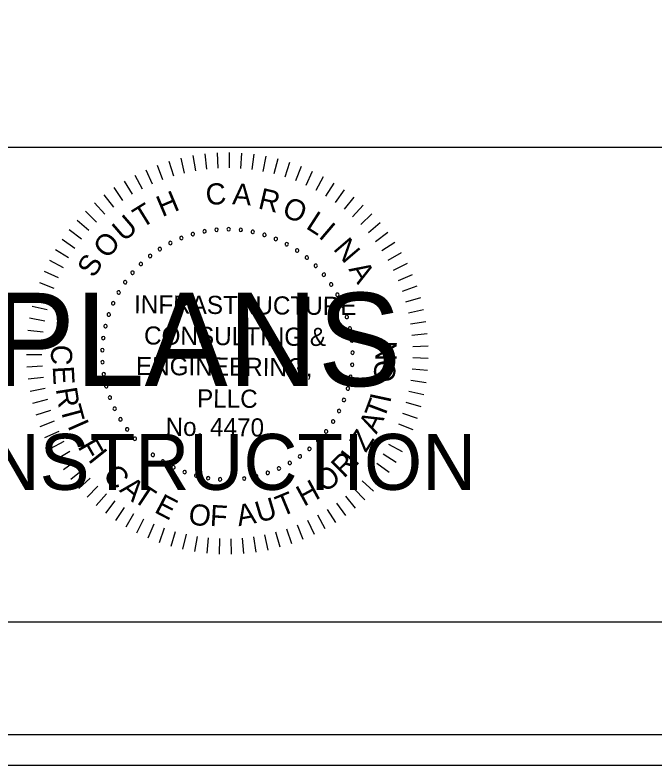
# Model space of a CAD drawing. Extents: x 967 to 1326, y 964 to 3704.
# Drawn here: x 1189.3 to 1212.88, y 963.72 to 991.36 of the extents above; entities that cross this region are included whole.
import ezdxf

# ---------------------------------------------------------------- set-up
doc = ezdxf.new("R2010")
doc.units = 0
for name, color, linetype in [('RD_SHT_Bndy', 7, 'Continuous'), ('RD_SHT_IplotShp', 7, 'Continuous'), ('RD_SHT_Misc1', 7, 'Continuous'), ('RD_SHT_Misc2', 7, 'Continuous'), ('RD_XS_TX_Station', 7, 'Continuous')]:
    doc.layers.add(name, color=color, linetype=linetype)

msp = doc.modelspace()

# ---------------------------------------------------------------- linework, layer by layer
at = {"layer": 'RD_SHT_Bndy'}
for p, q in [((996.114, 986.486), (1323.886, 986.486)), ((1323.886, 968.983), (996.114, 968.983))]:
    msp.add_line(p, q, dxfattribs=at)
at = {"layer": 'RD_SHT_IplotShp'}
for points in [[(967.409, 963.72), (1326.285, 963.72), (1326.285, 1183.72), (967.409, 1183.72)], [(988.525, 964.84), (1326.285, 964.84), (1326.285, 1182.6), (988.525, 1182.6)]]:
    msp.add_lwpolyline(points, close=True, dxfattribs=at)
at = {"layer": 'RD_SHT_Misc1'}
for p, q in [((1196.292, 986.245), (1196.357, 985.68)), ((1196.742, 986.282), (1196.772, 985.714)), ((1197.194, 986.292), (1197.189, 985.723)), ((1197.645, 986.274), (1197.606, 985.706)), ((1198.094, 986.228), (1198.02, 985.664)), ((1194.968, 985.971), (1195.134, 985.427)), ((1195.403, 986.09), (1195.536, 985.536)), ((1195.846, 986.181), (1195.945, 985.62)), ((1198.54, 986.156), (1198.432, 985.596)), ((1198.98, 986.056), (1198.838, 985.504)), ((1199.414, 985.929), (1199.238, 985.387)), ((1194.122, 985.656), (1194.353, 985.136)), ((1194.54, 985.827), (1194.739, 985.293)), ((1199.839, 985.777), (1199.63, 985.246)), ((1193.715, 985.461), (1193.978, 984.956)), ((1200.253, 985.598), (1200.013, 985.082)), ((1200.656, 985.395), (1200.385, 984.894)), ((1193.321, 985.241), (1193.614, 984.752)), ((1201.047, 985.167), (1200.745, 984.684)), ((1192.94, 984.997), (1193.263, 984.528)), ((1201.422, 984.917), (1201.092, 984.453)), ((1192.576, 984.731), (1192.926, 984.282)), ((1201.781, 984.643), (1201.424, 984.2)), ((1192.228, 984.443), (1192.605, 984.016)), ((1202.124, 984.349), (1201.739, 983.928)), ((1191.899, 984.134), (1192.301, 983.731)), ((1202.447, 984.034), (1202.038, 983.638)), ((1191.589, 983.805), (1192.015, 983.428)), ((1202.751, 983.7), (1202.318, 983.329)), ((1191.299, 983.459), (1191.748, 983.108)), ((1203.034, 983.348), (1202.579, 983.004)), ((1191.032, 983.095), (1191.501, 982.772)), ((1203.294, 982.979), (1202.82, 982.664)), ((1190.787, 982.716), (1191.274, 982.422)), ((1203.532, 982.595), (1203.04, 982.31)), ((1190.565, 982.323), (1191.07, 982.059)), ((1203.746, 982.198), (1203.237, 981.943)), ((1190.368, 981.916), (1190.888, 981.684)), ((1203.936, 981.788), (1203.412, 981.564)), ((1190.196, 981.499), (1190.729, 981.299)), ((1204.1, 981.367), (1203.563, 981.176)), ((1190.05, 981.072), (1190.594, 980.905)), ((1204.238, 980.937), (1203.691, 980.779)), ((1189.93, 980.636), (1190.484, 980.503)), ((1204.349, 980.5), (1203.794, 980.375)), ((1189.837, 980.195), (1190.398, 980.095)), ((1204.434, 980.056), (1203.872, 979.966)), ((1189.771, 979.748), (1190.337, 979.683)), ((1204.491, 979.608), (1203.925, 979.552)), ((1189.732, 979.298), (1190.301, 979.267)), ((1204.522, 979.158), (1203.953, 979.137)), ((1189.721, 978.847), (1190.29, 978.851)), ((1204.524, 978.706), (1203.955, 978.72)), ((1189.737, 978.396), (1190.306, 978.434)), ((1204.499, 978.256), (1203.932, 978.304)), ((1189.781, 977.946), (1190.346, 978.019)), ((1204.447, 977.807), (1203.884, 977.89)), ((1189.852, 977.5), (1190.412, 977.608)), ((1204.367, 977.363), (1203.81, 977.479)), ((1189.951, 977.06), (1190.502, 977.201)), ((1204.261, 976.924), (1203.712, 977.074)), ((1190.076, 976.626), (1190.617, 976.8)), ((1204.128, 976.492), (1203.589, 976.676)), ((1190.227, 976.2), (1190.757, 976.408)), ((1203.969, 976.07), (1203.442, 976.286)), ((1190.403, 975.785), (1190.92, 976.024)), ((1203.784, 975.658), (1203.271, 975.906)), ((1190.605, 975.381), (1191.106, 975.651)), ((1203.574, 975.258), (1203.078, 975.537)), ((1190.831, 974.99), (1191.315, 975.291)), ((1203.341, 974.871), (1202.862, 975.18)), ((1191.081, 974.614), (1191.545, 974.943)), ((1191.353, 974.253), (1191.796, 974.61)), ((1203.085, 974.5), (1202.626, 974.837)), ((1202.806, 974.145), (1202.368, 974.509)), ((1191.646, 973.91), (1192.067, 974.293)), ((1202.506, 973.807), (1202.092, 974.197)), ((1191.96, 973.585), (1192.356, 973.994)), ((1202.186, 973.488), (1201.796, 973.903)), ((1192.293, 973.28), (1192.664, 973.712)), ((1201.847, 973.19), (1201.484, 973.628)), ((1192.644, 972.996), (1192.988, 973.45)), ((1193.011, 972.734), (1193.327, 973.208)), ((1201.491, 972.912), (1201.155, 973.372)), ((1193.394, 972.495), (1193.68, 972.987)), ((1200.731, 972.425), (1200.453, 972.922)), ((1201.119, 972.657), (1200.811, 973.136)), ((1193.791, 972.279), (1194.047, 972.788)), ((1200.331, 972.217), (1200.083, 972.73)), ((1194.2, 972.088), (1194.424, 972.612)), ((1194.62, 971.923), (1194.812, 972.459)), ((1199.495, 971.877), (1199.312, 972.416)), ((1199.918, 972.034), (1199.702, 972.561)), ((1195.05, 971.783), (1195.208, 972.33)), ((1195.487, 971.67), (1195.612, 972.225)), ((1195.93, 971.584), (1196.021, 972.146)), ((1196.377, 971.524), (1196.434, 972.091)), ((1198.179, 971.562), (1198.097, 972.126)), ((1198.624, 971.64), (1198.508, 972.198)), ((1199.063, 971.745), (1198.913, 972.295)), ((1196.828, 971.493), (1196.85, 972.062)), ((1197.279, 971.488), (1197.267, 972.058)), ((1197.73, 971.512), (1197.683, 972.079))]:
    msp.add_line(p, q, dxfattribs=at)
for centre, start, end in [((1196.285, 983.388), 10.6038, 190.6038), ((1196.727, 983.447), 5.0653, 185.0653), ((1196.727, 983.447), 185.0653, 5.0653), ((1197.172, 983.464), 359.5268, 179.5268), ((1197.172, 983.464), 179.5268, 359.5268), ((1197.617, 983.438), 173.9884, 353.9884), ((1197.617, 983.438), 353.9884, 173.9884), ((1198.057, 983.369), 348.4499, 168.4499), ((1195.429, 983.142), 21.6807, 201.6807), ((1195.429, 983.142), 201.6807, 21.6807), ((1195.851, 983.285), 16.1422, 196.1422), ((1195.851, 983.285), 196.1422, 16.1422), ((1196.285, 983.388), 190.6038, 10.6038), ((1198.057, 983.369), 168.4499, 348.4499), ((1198.489, 983.258), 162.9114, 342.9114), ((1198.489, 983.258), 342.9114, 162.9114), ((1198.908, 983.106), 337.373, 157.373), ((1195.023, 982.958), 27.2191, 207.2191), ((1195.023, 982.958), 207.2191, 27.2191), ((1198.908, 983.106), 157.373, 337.373), ((1199.31, 982.914), 151.8345, 331.8345), ((1199.31, 982.914), 331.8345, 151.8345), ((1194.637, 982.736), 32.7576, 212.7576), ((1194.637, 982.736), 212.7576, 32.7576), ((1199.692, 982.684), 146.2961, 326.2961), ((1199.692, 982.684), 326.2961, 146.2961), ((1194.274, 982.478), 38.2961, 218.2961), ((1194.274, 982.478), 218.2961, 38.2961), ((1200.05, 982.419), 140.7576, 320.7576), ((1200.05, 982.419), 320.7576, 140.7576), ((1193.937, 982.186), 43.8345, 223.8345), ((1193.937, 982.186), 223.8345, 43.8345), ((1200.38, 982.12), 135.2191, 315.2191), ((1200.38, 982.12), 315.2191, 135.2191), ((1193.63, 981.862), 49.373, 229.373), ((1193.63, 981.862), 229.373, 49.373), ((1200.68, 981.79), 129.6807, 309.6807), ((1200.68, 981.79), 309.6807, 129.6807), ((1193.356, 981.511), 54.9114, 234.9114), ((1193.356, 981.511), 234.9114, 54.9114), ((1200.947, 981.433), 304.1422, 124.1422), ((1200.947, 981.433), 124.1422, 304.1422), ((1193.117, 981.135), 60.4499, 240.4499), ((1193.117, 981.135), 240.4499, 60.4499), ((1201.179, 981.052), 118.6038, 298.6038), ((1201.179, 981.052), 298.6038, 118.6038), ((1192.915, 980.737), 65.9884, 245.9884), ((1192.915, 980.737), 245.9884, 65.9884), ((1201.372, 980.651), 113.0653, 293.0653), ((1201.372, 980.651), 293.0653, 113.0653), ((1192.753, 980.322), 71.5268, 251.5268), ((1192.753, 980.322), 251.5268, 71.5268), ((1201.526, 980.233), 107.5268, 287.5268), ((1201.526, 980.233), 287.5268, 107.5268), ((1192.632, 979.894), 77.0653, 257.0653), ((1192.632, 979.894), 257.0653, 77.0653), ((1201.638, 979.801), 101.9884, 281.9884), ((1201.638, 979.801), 281.9884, 101.9884), ((1192.552, 979.455), 82.6038, 262.6038), ((1192.552, 979.455), 262.6038, 82.6038), ((1201.709, 979.361), 96.4499, 276.4499), ((1201.709, 979.361), 276.4499, 96.4499), ((1192.515, 979.011), 88.1422, 268.1422), ((1192.515, 979.011), 268.1422, 88.1422), ((1201.737, 978.917), 90.9114, 270.9114), ((1201.737, 978.917), 270.9114, 90.9114), ((1192.522, 978.565), 93.6807, 273.6807), ((1192.522, 978.565), 273.6807, 93.6807), ((1201.721, 978.471), 85.373, 265.373), ((1201.721, 978.471), 265.373, 85.373), ((1192.571, 978.122), 99.2191, 279.2191), ((1192.571, 978.122), 279.2191, 99.2191), ((1201.663, 978.029), 79.8345, 259.8345), ((1201.663, 978.029), 259.8345, 79.8345), ((1192.662, 977.686), 104.7576, 284.7576), ((1192.662, 977.686), 284.7576, 104.7576), ((1201.563, 977.595), 74.2961, 254.2961), ((1201.563, 977.595), 254.2961, 74.2961), ((1192.796, 977.261), 110.2961, 290.2961), ((1192.796, 977.261), 290.2961, 110.2961), ((1201.42, 977.173), 68.7576, 248.7576), ((1201.42, 977.173), 248.7576, 68.7576), ((1192.97, 976.851), 115.8345, 295.8345), ((1192.97, 976.851), 295.8345, 115.8345), ((1201.238, 976.766), 63.2191, 243.2191), ((1201.238, 976.766), 243.2191, 63.2191), ((1193.182, 976.459), 301.373, 121.373), ((1193.182, 976.459), 121.373, 301.373), ((1201.018, 976.379), 57.6807, 237.6807), ((1201.018, 976.379), 237.6807, 57.6807), ((1193.432, 976.09), 126.9114, 306.9114), ((1193.432, 976.09), 306.9114, 126.9114), ((1200.761, 976.014), 52.1422, 232.1422), ((1200.761, 976.014), 232.1422, 52.1422), ((1193.715, 975.746), 132.4499, 312.4499), ((1193.715, 975.746), 312.4499, 132.4499), ((1200.47, 975.677), 46.6038, 226.6038), ((1200.47, 975.677), 226.6038, 46.6038), ((1194.031, 975.431), 137.9884, 317.9884), ((1194.031, 975.431), 317.9884, 137.9884), ((1200.148, 975.369), 41.0653, 221.0653), ((1200.148, 975.369), 221.0653, 41.0653), ((1194.376, 975.149), 143.5268, 323.5268), ((1194.376, 975.149), 323.5268, 143.5268), ((1199.798, 975.093), 35.5268, 215.5268), ((1194.746, 974.901), 149.0653, 329.0653), ((1194.746, 974.901), 329.0653, 149.0653), ((1199.422, 974.853), 29.9884, 209.9884), ((1199.422, 974.853), 209.9884, 29.9884), ((1199.798, 975.093), 215.5268, 35.5268), ((1195.139, 974.69), 154.6038, 334.6038), ((1195.139, 974.69), 334.6038, 154.6038), ((1195.55, 974.517), 340.1422, 160.1422), ((1199.026, 974.65), 24.4499, 204.4499), ((1199.026, 974.65), 204.4499, 24.4499), ((1195.55, 974.517), 160.1422, 340.1422), ((1195.975, 974.386), 165.6807, 345.6807), ((1195.975, 974.386), 345.6807, 165.6807), ((1196.412, 974.295), 171.2191, 351.2191), ((1196.412, 974.295), 351.2191, 171.2191), ((1196.855, 974.248), 356.7576, 176.7576), ((1197.301, 974.243), 2.2961, 182.2961), ((1197.745, 974.282), 7.8345, 187.8345), ((1198.183, 974.363), 13.373, 193.373), ((1198.183, 974.363), 193.373, 13.373), ((1198.611, 974.486), 18.9114, 198.9114), ((1198.611, 974.486), 198.9114, 18.9114), ((1196.855, 974.248), 176.7576, 356.7576), ((1197.301, 974.243), 182.2961, 2.2961), ((1197.745, 974.282), 187.8345, 7.8345)]:
    msp.add_arc(centre, 0.0627, start, end, dxfattribs=at)
at = {"layer": 'RD_XS_TX_Station'}
msp.add_lwpolyline([(967.409, 963.72), (1326.285, 963.72), (1326.285, 1183.72), (967.409, 1183.72)], close=True, dxfattribs=at)

# ---------------------------------------------------------------- texts
at = {"layer": 'RD_SHT_Misc1'}
for s, height, rotation, p in [('C', 0.78, 4.7281, (1196.355, 984.346)), ('A', 0.78, 355.6981, (1197.29, 984.39)), ('H', 0.78, 22.7882, (1194.72, 983.904)), ('R', 0.78, 346.6681, (1198.222, 984.238)), ('O', 0.78, 337.638, (1199.096, 983.972)), ('T', 0.78, 31.8182, (1193.961, 983.478)), ('U', 0.78, 40.8482, (1193.306, 982.976)), ('L', 0.78, 327.108, (1199.981, 983.52)), ('I', 0.78, 319.578, (1200.451, 983.182)), ('O', 0.78, 49.8782, (1192.707, 982.341)), ('N', 0.78, 310.548, (1200.994, 982.728)), ('S', 0.78, 58.9083, (1192.211, 981.642)), ('A', 0.78, 301.5179, (1201.576, 981.991)), ('INFRASTRUCTURE', 0.66873, 359.5268, (1193.682, 980.367)), ('CONSULTING &', 0.66873, 359.5268, (1194.051, 979.217)), ('N', 0.78, 89.2085, (1203.359, 978.604)), ('C', 0.78, 267.025, (1190.646, 979.227)), ('ENGINEERING,', 0.66873, 359.5268, (1193.751, 978.095)), ('O', 0.78, 83.2085, (1203.26, 977.786)), ('E', 0.78, 273.025, (1190.685, 978.408)), ('R', 0.78, 279.025, (1190.799, 977.583)), ('PLLC', 0.6687, 359.5268, (1196.002, 976.9)), ('I', 0.78, 77.9093, (1203.121, 977.032)), ('T', 0.78, 69.3954, (1202.891, 976.428)), ('T', 0.78, 285.025, (1190.955, 976.878)), ('No. 4470', 0.6687, 359.5268, (1194.843, 975.855)), ('A', 0.78, 63.3954, (1202.616, 975.888)), ('I', 0.78, 293.7713, (1191.221, 976.225)), ('Z', 0.78, 57.3954, (1202.224, 975.206)), ('F', 0.78, 299.7713, (1191.589, 975.455)), ('I', 0.78, 308.5268, (1191.965, 974.973)), ('R', 0.78, 44.5268, (1201.415, 974.267)), ('I', 0.78, 52.3339, (1201.856, 974.69)), ('C', 0.78, 314.5268, (1192.496, 974.346)), ('O', 0.78, 38.5268, (1200.73, 973.731)), ('A', 0.78, 320.5268, (1193.115, 973.822)), ('T', 0.78, 326.5268, (1193.602, 973.478)), ('H', 0.78, 28.5268, (1199.942, 973.23)), ('T', 0.78, 22.5268, (1199.108, 972.856)), ('E', 0.78, 332.5268, (1194.394, 973.051)), ('U', 0.78, 16.5268, (1198.288, 972.638)), ('O', 0.78, 350.5268, (1195.647, 972.614)), ('F', 0.78, 356.5268, (1196.465, 972.532)), ('A', 0.78, 10.5268, (1197.537, 972.517))]:
    msp.add_text(s, height=height, rotation=rotation, dxfattribs=at).set_placement(p)
at = {"layer": 'RD_SHT_Misc2'}
for s, height, p in [('FINAL PLANS', 3.4375, (1174.145, 977.685)), ('NOT FOR CONSTRUCTION', 2.0625, (1170.901, 973.86))]:
    msp.add_text(s, height=height, dxfattribs=at).set_placement(p)

doc.saveas('drawing.dxf')
